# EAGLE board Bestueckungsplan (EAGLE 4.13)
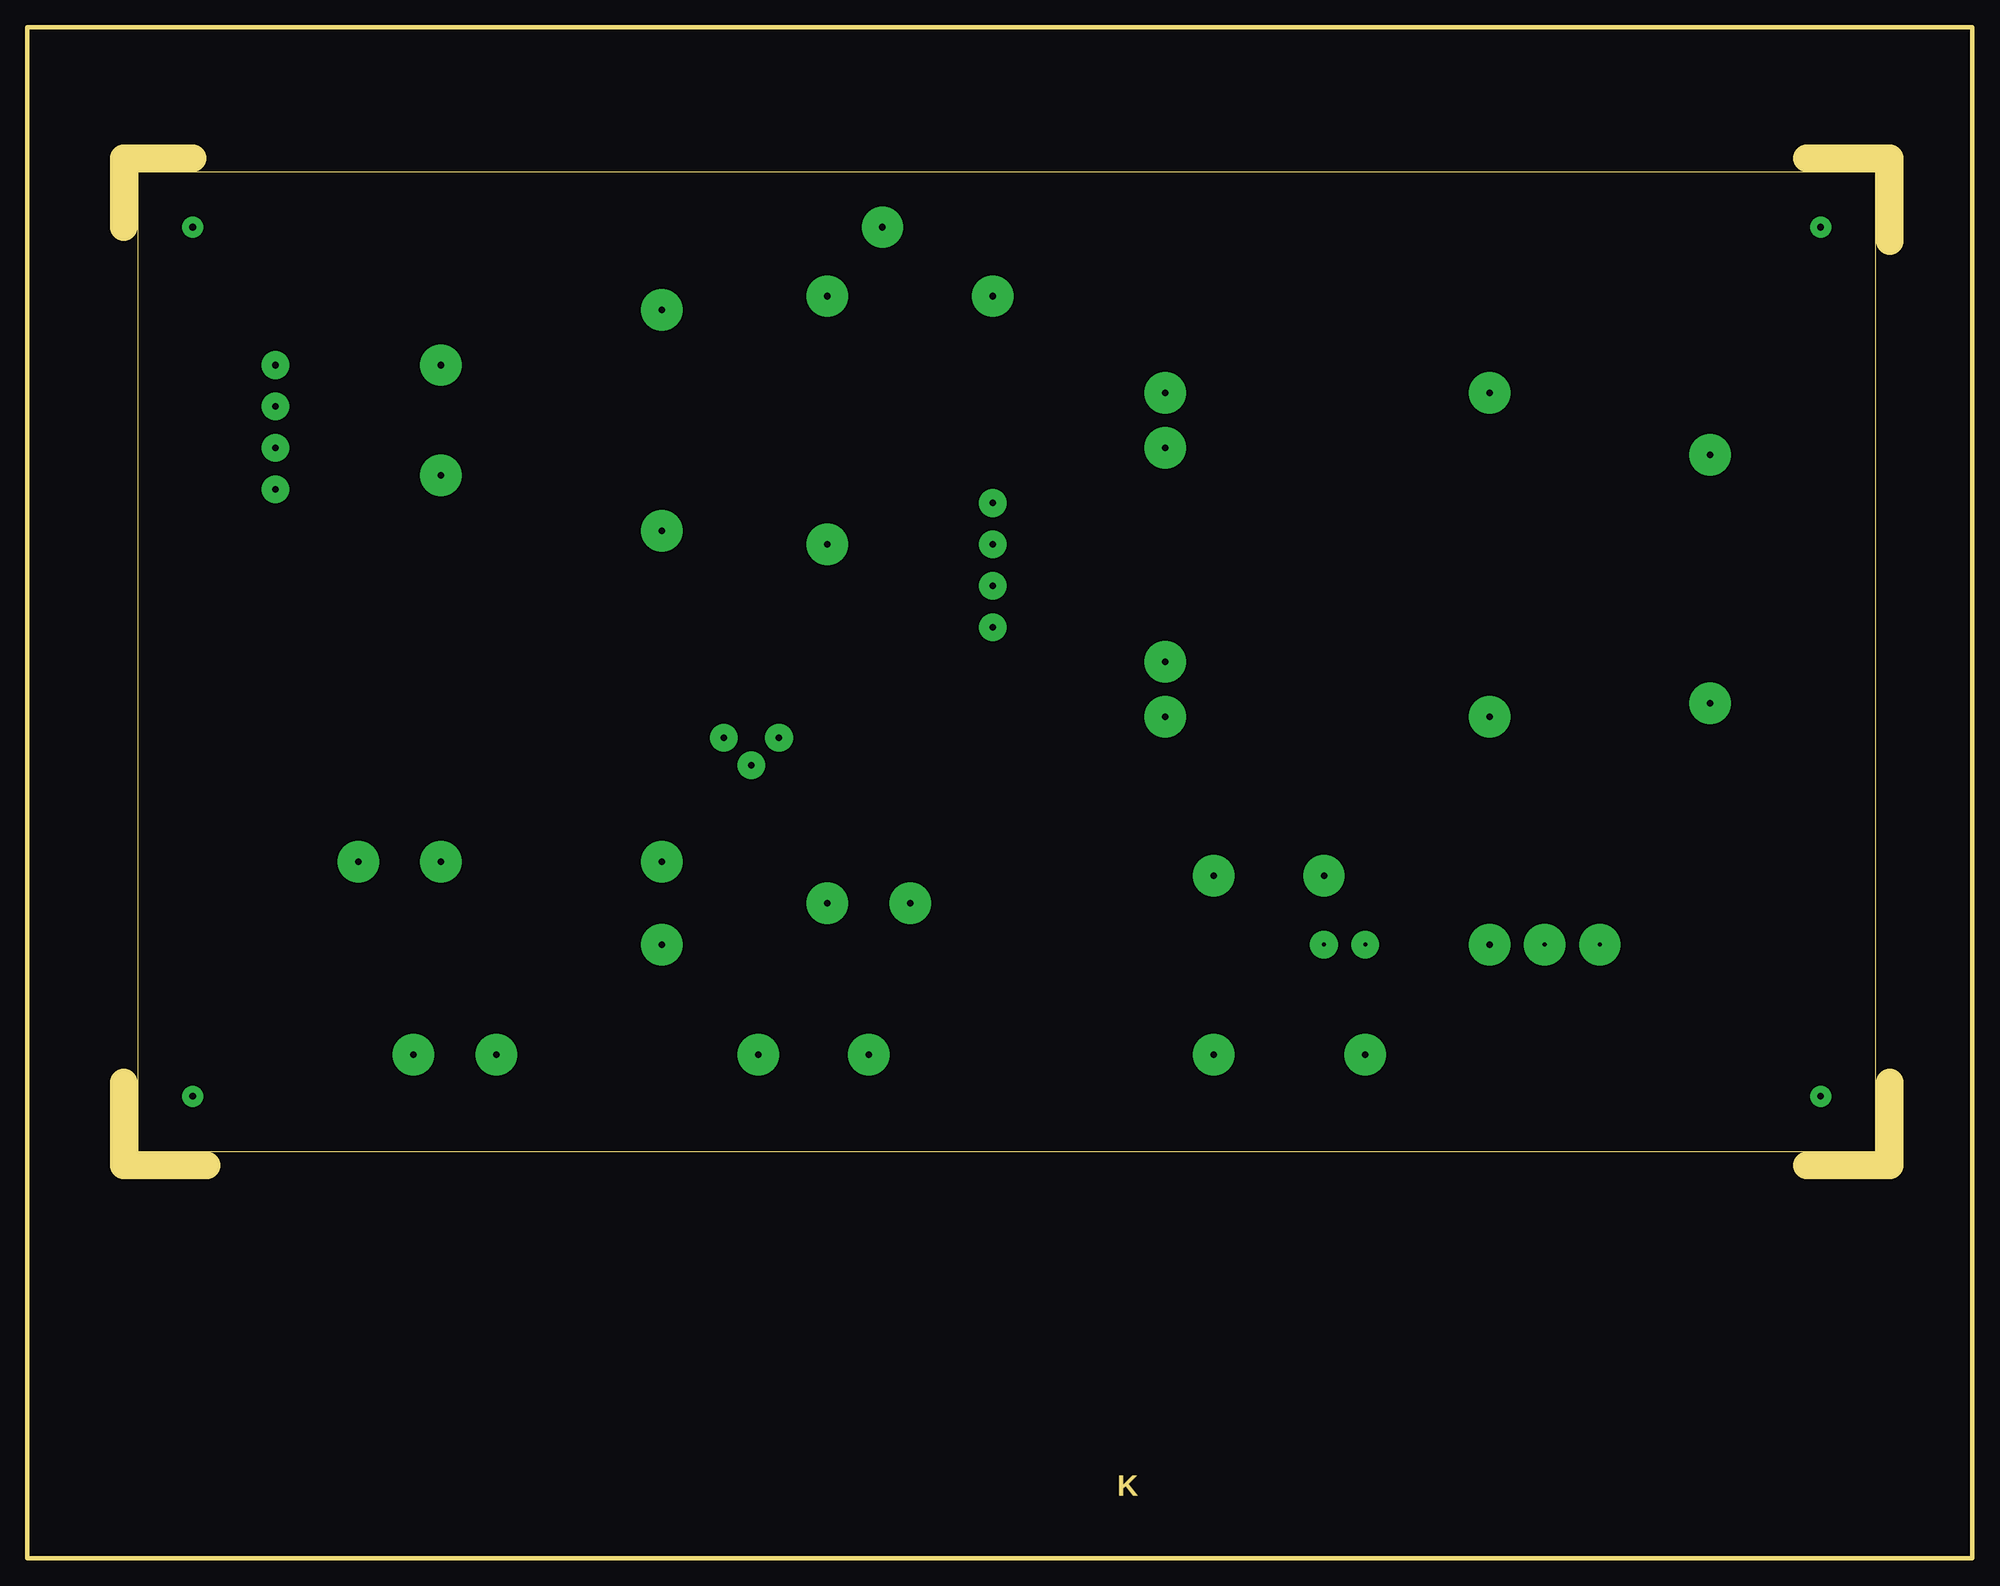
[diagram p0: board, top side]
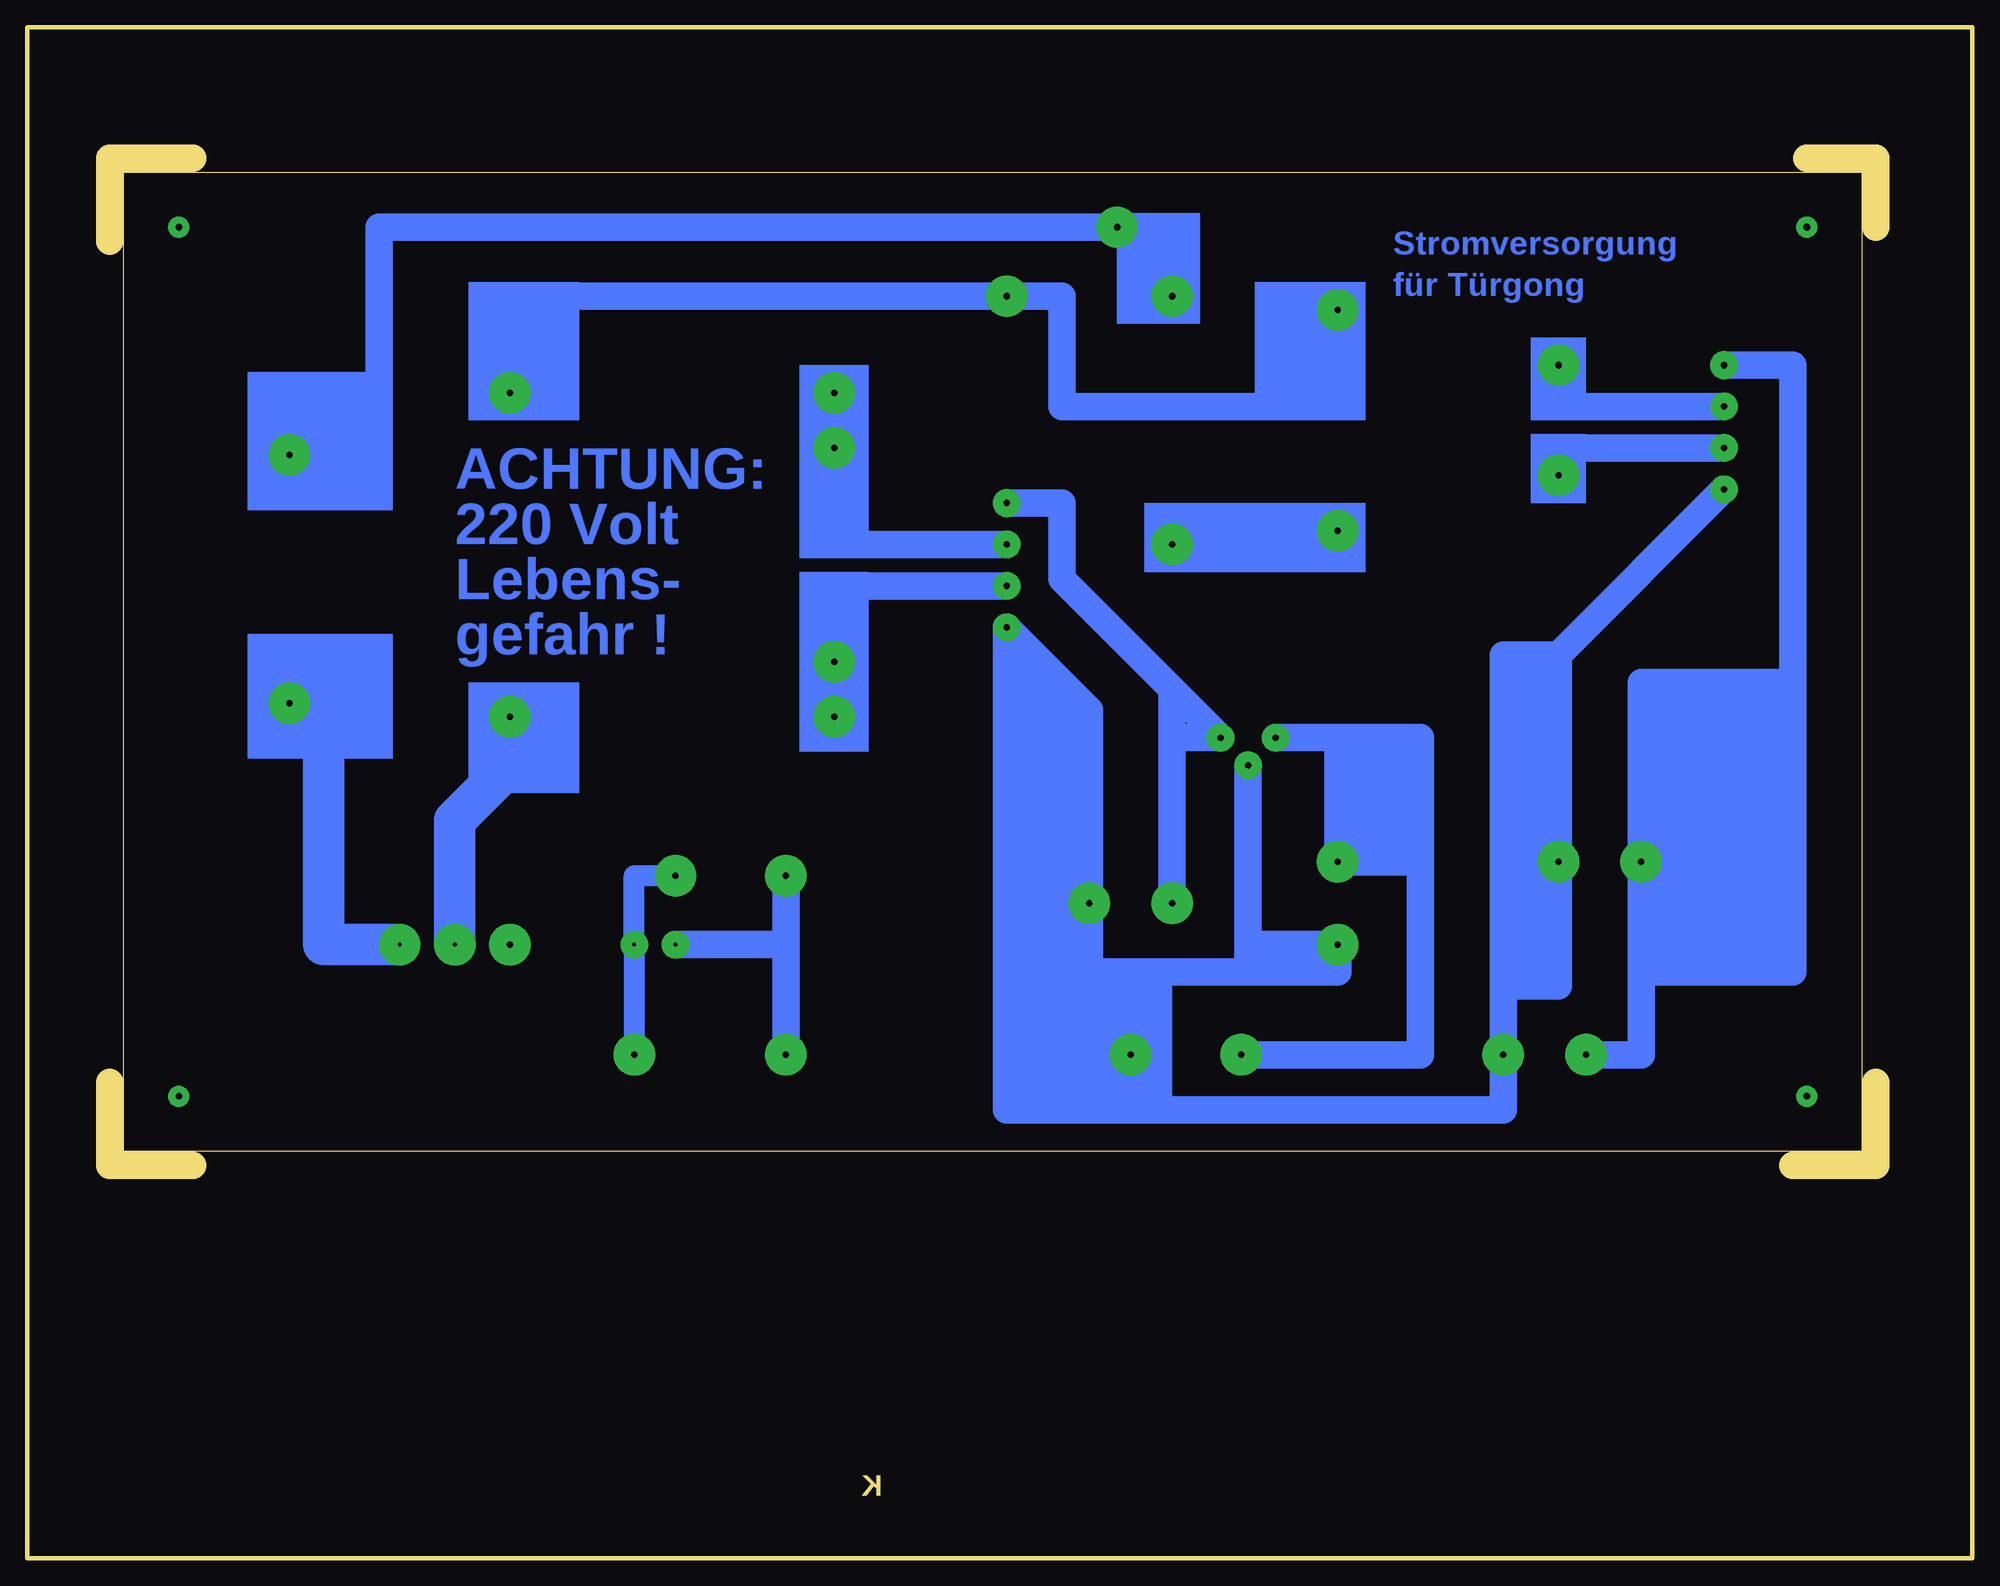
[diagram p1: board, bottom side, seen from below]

Size 179.07 x 140.97 mm. Coordinates in mm from the lower left corner, seen from the top.
Outline: 15.24,128.91 8.89,128.91 8.89,122.56
Outline: 163.83,128.91 171.45,128.91 171.45,121.28
Outline: 8.89,43.82 8.89,36.2 16.51,36.2
Outline: 163.83,36.2 171.45,36.2 171.45,43.82
Outline: 0,140.97 179.07,140.97 179.07,0 0,0 0,140.97
Outline: 10.16,37.47 170.18,37.47 170.18,127.64 10.16,127.64 10.16,37.47
Copper layers (1*16): Top 0.035mm / dielectric 1.5mm / Bottom 0.035mm
Design rules "default": minimum track width 10mil, minimum drill 24mil, track to track 8mil, track to pad 8mil, pad to pad 8mil, via to via 8mil, smd to smd 8mil, copper to edge 40mil, drill to drill 8mil, minimum pad ring 10mil, minimum via ring 8mil, stop-mask expansion 4mil, vias tented up to drill 0mil, thermal gap 10mil

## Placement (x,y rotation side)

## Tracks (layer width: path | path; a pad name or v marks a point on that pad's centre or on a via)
S$1  (via drill 0.6 pad 1.93)
  other vias: 15.24,42.55
S$2  (via drill 0.6 pad 1.93)
  other vias: 15.24,122.56
S$3  (via drill 0.6 pad 1.93)
  other vias: 165.1,42.55
S$4  (via drill 0.6 pad 1.93)
  other vias: 165.1,122.56
S$5  (via drill 0.6 pad 1.93)
  other vias: 15.24,42.55
S$6  (via drill 0.6 pad 1.93)
  other vias: 15.24,122.56
S$7  (via drill 0.6 pad 3.81)
  other vias: 154.94,101.6
S$9  (via drill 0.6 pad 3.81)
  other vias: 104.78,107.31
S$10  (via drill 0.6 pad 3.81)
  other vias: 104.78,77.47
S$11  (via drill 0.6 pad 3.81)
  other vias: 154.94,78.74
S$12  (via drill 0.6 pad 3.81)
  other vias: 134.62,77.47
S$13  (via drill 0.6 pad 3.81)
  other vias: 73.66,60.33
S$14  (via drill 0.6 pad 3.81)
  other vias: 104.78,102.23
S$15  (via drill 0.6 pad 3.81)
  other vias: 104.78,82.55
S$16  (via drill 0.6 pad 2.54)
  other vias: 88.9,97.16
S$17  (via drill 0.6 pad 2.54)
  other vias: 88.9,93.34
S$18  (via drill 0.6 pad 2.54)
  other vias: 88.9,89.53
S$19  (via drill 0.6 pad 3.81)
  other vias: 73.66,93.34
S$20  (via drill 0.6 pad 1.93)
  other vias: 165.1,42.55
S$21  (via drill 0.6 pad 3.81)
  other vias: 58.42,94.62
S$22  (via drill 0.6 pad 3.81)
  other vias: 58.42,114.94
S$23  (via drill 0.6 pad 1.93)
  other vias: 165.1,122.56
S$24  (via drill 0.6 pad 3.81)
  other vias: 134.62,56.52
S$25  (via drill 0.6 pad 3.81)
  other vias: 38.1,109.86
S$26  (via drill 0.6 pad 3.81)
  other vias: 38.1,99.69
S$27  (via drill 0.6 pad 3.81)
  Bottom 3.81: 147.32,78.74 v154.94,78.74
S$28  (via drill 0.6 pad 3.81)
  other vias: 104.78,107.31
S$30  (via drill 0.6 pad 3.81)
  other vias: 104.78,77.47
S$31  (via drill 0.6 pad 2.54)
  other vias: 22.86,109.86
S$32  (via drill 0.6 pad 2.54)
  other vias: 22.86,106.05
S$33  (via drill 0.6 pad 2.54)
  other vias: 22.86,102.23
S$34  (via drill 0.6 pad 2.54)
  other vias: 22.86,98.43
S$36  (via drill 0.6 pad 2.54, 0.6 pad 3.81)
  Bottom 2.54: v88.9,97.16 83.82,97.16 83.82,90.17 v69.22,75.56 73.66,75.56 | v73.66,60.33 73.66,69.22 | 73.66,75.56 73.66,77.47 | 73.66,77.47 73.66,79.38 | 73.66,75.56 73.66,69.22 | 73.66,69.22 73.66,77.47
S$38  (via drill 0.6 pad 3.81)
  other vias: 67.31,46.36
S$39  (via drill 0.6 pad 3.81)
  other vias: 73.66,116.2
S$40  (via drill 0.6 pad 3.81)
  other vias: 77.47,46.36
S$41  (via drill 0.6 pad 2.54)
  other vias: 69.22,75.56
S$42  (via drill 0.6 pad 3.81)
  other vias: 134.62,107.31
S$43  (via drill 0.6 pad 3.81)
  other vias: 35.56,46.36
S$44  (via drill 0.6 pad 3.81)
  other vias: 58.42,56.52
S$46  (via drill 0.6 pad 2.54)
  other vias: 64.14,75.56
S$47  (via drill 0.6 pad 3.81)
  other vias: 78.74,122.56
S$48  (via drill 0.6 pad 3.81)
  other vias: 88.9,116.2
S$49  (via drill 0.6 pad 3.81)
  other vias: 30.48,64.14
S$50  (via drill 0.6 pad 2.54)
  other vias: 66.68,73.03
S$51  (via drill 0.6 pad 3.81)
  other vias: 58.42,64.14
S$52  (via drill 0.6 pad 3.81)
  other vias: 81.28,60.33
S$53  (via drill 0.6 pad 2.54)
  other vias: 88.9,85.72
S$54  (via drill 0.6 pad 3.81)
  other vias: 38.1,64.14
S$55  (via drill 0.6 pad 3.81)
  other vias: 43.18,46.36
S$56  (via drill 0.6 pad 2.54, 0.6 pad 3.81)
  Bottom 2.54: v88.9,93.34 104.78,93.34 v104.78,102.23
S$57  (via drill 0.6 pad 2.54, 0.6 pad 3.81)
  Bottom 2.54: v88.9,89.53 104.78,89.53 v104.78,82.55
S$58  (via drill 0.6 pad 3.81)
  Bottom 3.81: v58.42,94.62 72.39,94.62 v73.66,93.34
S$59  (via drill 0.6 pad 3.81)
  Bottom 2.54: v58.42,114.94 58.42,106.05 83.82,106.05 83.82,116.2 v88.9,116.2 134.62,116.2 v134.62,107.31
S$60  (via drill 0.6 pad 2.54, 0.6 pad 3.81)
  Bottom 2.54: v22.86,109.86 16.51,109.86 16.51,80.65 | 16.51,80.65 16.51,64.14 | v35.56,46.36 30.48,46.36 30.48,53.98 | 30.48,53.98 v30.48,64.14 | v30.48,64.14 16.51,64.14 | 16.51,64.14 16.51,53.98 30.48,53.98 | 16.51,80.65 30.48,80.65 v30.48,64.14
S$61  (via drill 0.6 pad 2.54, 0.6 pad 3.81)
  Bottom 2.54: v22.86,106.05 38.1,106.05 v38.1,109.86
S$62  (via drill 0.6 pad 2.54, 0.6 pad 3.81)
  Bottom 2.54: v22.86,102.23 38.1,102.23 v38.1,99.69
S$63  (via drill 0.6 pad 2.54, 0.6 pad 3.81)
  Bottom 2.54: v22.86,98.43 38.1,83.19 | 43.18,64.14 v38.1,64.14 38.1,83.19 | 43.18,64.14 43.18,52.7 | 43.18,52.7 v43.18,46.36 43.18,41.27 74.93,41.27 | 43.18,52.7 38.1,52.7 38.1,63.5 | v66.68,73.03 66.68,56.52 | 66.68,53.98 74.93,53.98 | 74.93,53.98 81.28,53.98 | 81.28,75.56 81.28,78.11 v88.9,85.72 88.9,41.27 81.28,41.27 | 81.28,75.56 v81.28,60.33 81.28,53.98 | 81.28,53.98 81.28,46.36 | 74.93,46.36 74.93,53.98 | v58.42,56.52 59.05,56.52 | 59.05,56.52 66.68,56.52 | 66.68,56.52 66.68,53.98 | 66.68,53.98 58.42,53.98 58.42,55.88 59.05,55.88 59.05,56.52 | 59.05,56.52 65.41,56.52 65.41,55.25 | 74.93,46.36 81.28,46.36 | 81.28,46.36 81.28,41.27 | 81.28,41.27 74.93,41.27 | 74.93,41.27 74.93,46.36 | 81.28,41.27 81.28,75.56 | 81.28,75.56 88.27,83.19 88.27,80.65 81.91,73.66 81.91,71.75 88.27,78.11 | 38.1,83.19 43.18,83.19 43.18,64.14
S$64  (via drill 0.6 pad 2.54, 0.6 pad 3.81)
  Bottom 2.54: 50.8,64.14 v58.42,64.14 58.42,75.56 | 50.8,64.14 50.8,46.36 v67.31,46.36 | 50.8,64.14 50.8,75.56 58.42,75.56 | v64.14,75.56 58.42,75.56
S$65  (via drill 0.6 pad 3.81)
  other vias: 77.47,46.36
S$66  (via drill 0.6 pad 3.81)
  Bottom 2.54: v73.66,116.2 73.66,122.56 v78.74,122.56 146.69,122.56 146.69,108.59
S$67  (via drill 0.6 pad 3.81)
  other vias: 154.94,101.6
S$68  (via drill 0.6 pad 3.81)
  other vias: 123.19,46.36 109.22,46.36
S$69  (via drill 0.6 pad 3.81)
  other vias: 134.62,77.47
S$70  (via drill 0.4 pad 3.81)
  Bottom 3.81: v144.78,56.52 151.76,56.52 151.76,74.3
S$71  (via drill 0.4 pad 3.81)
  Bottom 3.81: v139.7,56.52 139.7,67.94 135.89,71.75
S$72  (via drill 0.4 pad 3.81)
  other vias: 134.62,56.52
S$73  (via drill 0.4 pad 2.54, 0.6 pad 3.81)
  Bottom 2.54: 109.22,56.52 v119.38,56.52 | 109.22,56.52 v109.22,62.87 | 109.22,46.36 109.22,56.52
S$74  (via drill 0.4 pad 2.54, 0.6 pad 3.81)
  Bottom 1.93: v119.38,62.87 123.19,62.87 v123.19,56.52 123.19,46.36
(copper drawn outside any net)
  shapes: Bottom area x18

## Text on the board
Bottom: Stromversorgung | für Türgong | ACHTUNG: | 220 Volt | Lebens- | gefahr !
Dimension: K
tOrigins: 220Volt | Netzspannung | + | Trafo | AC | 8V / 1,5W | + | - | Sicherung | 100mA | Gleichrichter | 230V/1.5A | AC | mit Sicherungshalter | - | Sicherung | 100mA | Gleichrichter | 230V/1.5A | Trafo | 12V / 16W | 78S12 | Ausg. | Eing. | mit Sicherungshalter | Elko | 2200µ/35V | + | Elko | 1N4002 | + | K | 4700µ/35V | + | Elko | 2200µ/35V | 5 Volt Relais | Masse | Masse | +14V | für Steuerplatine | +12V | für NF-Verst. | 78S12 | an +5V von Steuerplatine | Leiterplatte: | an Kollektor (BC547) von Steuerplatine | 1,5mm dick | Bohrungen: | Cevausit | alles 1,0mm | 1N4002 | Elko's | Lastrelais 1,5mm | Sicherungshalter 1,5mm | der lange Draht ist | 4Stck. Befestigungsbohr... 3,2mm | der + Pol | Eing. | Ausg. | Katode | Anode | Masse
